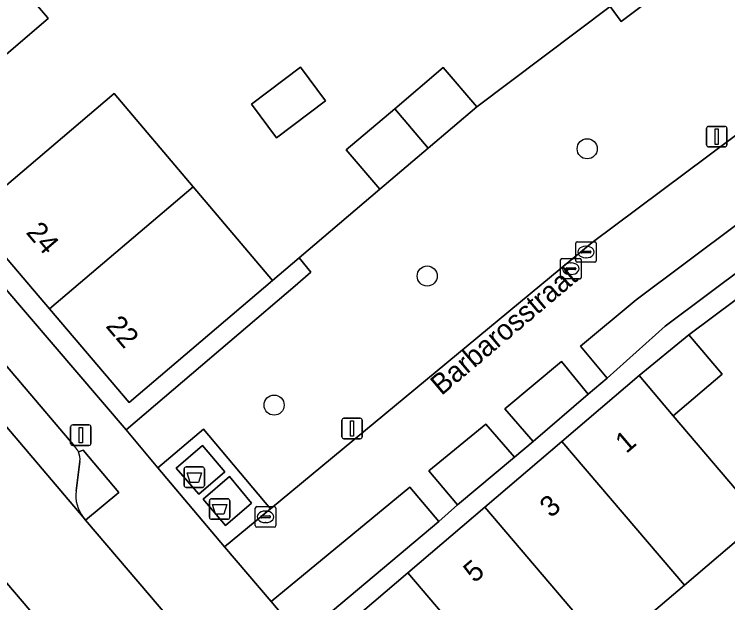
# Model space of a CAD drawing. Extents: x 160377 to 161131, y 383938 to 384853.
# Drawn here: x 160564.71 to 160599.42, y 384590.53 to 384619.15 of the extents above; entities that cross this region are included whole.
import ezdxf

# ---------------------------------------------------------------- set-up
doc = ezdxf.new("R2010")
doc.units = 0
for name, color, linetype in [('IMGEO_Afval_apart_plaats', 7, 'Continuous'), ('IMGEO_Boom', 7, 'Continuous'), ('IMGEO_Erf', 7, 'Continuous'), ('IMGEO_Groenvoorziening', 7, 'Continuous'), ('IMGEO_Kolk', 7, 'Continuous'), ('IMGEO_Lichtmast', 7, 'Continuous'), ('IMGEO_Openbare_ruimte_label', 7, 'Continuous'), ('IMGEO_Pand', 7, 'Continuous'), ('IMGEO_Pand_nummerreeks', 7, 'Continuous'), ('IMGEO_Parkeervlak_open', 7, 'Continuous'), ('IMGEO_Rijbaan_lokaal_open', 7, 'Continuous'), ('IMGEO_Rioolput', 7, 'Continuous'), ('IMGEO_Voetgangersgebied_open', 7, 'Continuous'), ('IMGEO_Voetpad_gesloten', 7, 'Continuous'), ('IMGEO_Voetpad_open', 7, 'Continuous')]:
    doc.layers.add(name, color=color, linetype=linetype)

msp = doc.modelspace()

# ---------------------------------------------------------------- linework, layer by layer
at = {"layer": 'IMGEO_Afval_apart_plaats'}
for p, q in [((160573.078, 384597.139), (160573.868, 384597.139)), ((160573.868, 384597.139), (160573.078, 384597.139)), ((160572.978, 384596.239), (160572.978, 384597.039)), ((160572.978, 384597.039), (160572.978, 384596.239)), ((160573.968, 384597.039), (160573.968, 384596.239)), ((160573.968, 384596.239), (160573.968, 384597.039)), ((160573.868, 384596.139), (160573.078, 384596.139)), ((160573.078, 384596.139), (160573.868, 384596.139)), ((160574.208, 384594.689), (160574.208, 384595.489)), ((160574.208, 384595.489), (160574.208, 384594.689)), ((160574.308, 384595.589), (160575.098, 384595.589)), ((160575.098, 384595.589), (160574.308, 384595.589)), ((160575.198, 384595.489), (160575.198, 384594.689)), ((160575.198, 384594.689), (160575.198, 384595.489)), ((160575.098, 384594.589), (160574.308, 384594.589)), ((160574.308, 384594.589), (160575.098, 384594.589))]:
    msp.add_line(p, q, dxfattribs=at)
for points in [[(160573.121, 384596.853), (160573.825, 384596.853), (160573.676, 384596.383), (160573.27, 384596.383), (160573.121, 384596.853)], [(160574.351, 384595.303), (160575.055, 384595.303), (160574.906, 384594.833), (160574.5, 384594.833), (160574.351, 384595.303)]]:
    msp.add_lwpolyline(points, dxfattribs=at)
for centre, start, end in [((160573.078, 384597.039), 90, 180), ((160573.078, 384597.039), 90, 180), ((160573.868, 384597.039), 0, 90), ((160573.868, 384597.039), 360, 90), ((160573.078, 384596.239), 180, 270), ((160573.078, 384596.239), 180, 270), ((160573.868, 384596.239), 270, 0), ((160573.868, 384596.239), 270, 0), ((160574.308, 384595.489), 90, 180), ((160574.308, 384595.489), 90, 180), ((160575.098, 384595.489), 0, 90), ((160575.098, 384595.489), 360, 90), ((160574.308, 384594.689), 180, 270), ((160574.308, 384594.689), 180, 270), ((160575.098, 384594.689), 270, 0), ((160575.098, 384594.689), 270, 0)]:
    msp.add_arc(centre, 0.1, start, end, dxfattribs=at)
at = {"layer": 'IMGEO_Boom'}
for centre in [(160592.589, 384612.611), (160584.803, 384606.421), (160577.354, 384600.144)]:
    msp.add_circle(centre, 0.489, dxfattribs=at)
at = {"layer": 'IMGEO_Erf'}
for points in [[(160593.711, 384619.536), (160594.236, 384618.794), (160600.544, 384623.533)], [(160562.78, 384623.153), (160566.325, 384618.994), (160566.361, 384618.952), (160559.441, 384613.028), (160559.422, 384613.011), (160558.691, 384612.377), (160561.787, 384608.701), (160562.572, 384609.354), (160569.566, 384615.295), (160573.423, 384610.752), (160577.28, 384606.208), (160578.569, 384607.304), (160582.493, 384610.638), (160580.864, 384612.554), (160583.222, 384614.558), (160585.584, 384616.565), (160587.217, 384614.645), (160593.711, 384619.536)], [(160591.976, 384574.85), (160586.069, 384581.798), (160580.11, 384588.786), (160583.86, 384591.983), (160587.609, 384595.179), (160591.358, 384598.376), (160595.112, 384601.577), (160597.527, 384603.553), (160604.448, 384608.711), (160611.793, 384614.232), (160615.064, 384609.881), (160618.338, 384605.528), (160621.611, 384601.175), (160624.884, 384596.822)], [(160624.091, 384582.595), (160620.818, 384586.948), (160617.544, 384591.3), (160614.27, 384595.653), (160610.996, 384600.006), (160607.722, 384604.358), (160604.448, 384608.711), (160597.527, 384603.553), (160599.148, 384601.649), (160596.772, 384599.627), (160601.065, 384594.584), (160597.316, 384591.387), (160593.567, 384588.191), (160596.062, 384585.072), (160592.408, 384581.957), (160589.818, 384584.995), (160586.069, 384581.798), (160591.976, 384574.85)]]:
    msp.add_lwpolyline(points, dxfattribs=at)
for points in [[(160578.635, 384616.574), (160579.852, 384614.949), (160577.464, 384613.145), (160576.251, 384614.774)], [(160656.048, 384504.315), (160656.893, 384504.376), (160651.516, 384563.083), (160634.758, 384585.358), (160611.972, 384615.646), (160608.482, 384613.028), (160596.383, 384603.983), (160593.555, 384601.453), (160592.642, 384600.679), (160589.954, 384598.377), (160589.048, 384597.617), (160586.272, 384595.285), (160585.368, 384594.478), (160578.674, 384588.862), (160588.469, 384577.392), (160609.42, 384552.826), (160611.199, 384533.452), (160614.226, 384500.488)], [(160578.387, 384605.942), (160579.15, 384606.609), (160578.569, 384607.304), (160577.28, 384606.208), (160570.304, 384600.269), (160566.433, 384604.818), (160562.572, 384609.354), (160561.787, 384608.701), (160570.15, 384598.933)]]:
    msp.add_lwpolyline(points, close=True, dxfattribs=at)
at = {"layer": 'IMGEO_Groenvoorziening'}
for points in [[(160605.23, 384617.306), (160600.544, 384623.533), (160594.236, 384618.794), (160593.711, 384619.536), (160587.217, 384614.645), (160584.857, 384612.643), (160582.493, 384610.638), (160578.569, 384607.304), (160579.15, 384606.609), (160578.387, 384605.942), (160570.15, 384598.933), (160571.697, 384597.097), (160573.915, 384598.966), (160577.172, 384595.101), (160592.826, 384608.058)], [(160608.482, 384613.028), (160607.339, 384614.528), (160594.964, 384605.267), (160592.267, 384603.016), (160593.555, 384601.453), (160596.383, 384603.983)], [(160592.642, 384600.679), (160591.339, 384602.256), (160588.574, 384599.969), (160589.954, 384598.377)], [(160589.048, 384597.617), (160587.656, 384599.213), (160584.883, 384596.943), (160586.272, 384595.285)], [(160585.368, 384594.478), (160583.958, 384596.145), (160577.214, 384590.588), (160578.674, 384588.862)]]:
    msp.add_lwpolyline(points, close=True, dxfattribs=at)
for points in [[(160568.066, 384594.689), (160568.182, 384594.551), (160569.797, 384595.89), (160568.06, 384597.946), (160567.836, 384597.868)], [(160567.905, 384597.403), (160567.721, 384595.973)]]:
    msp.add_lwpolyline(points, dxfattribs=at)
for centre, radius, start, end in [((160567.028, 384597.51), 0.884, 353.0213, 23.8595), ((160569.453, 384595.75), 1.746, 172.6643, 217.415)]:
    msp.add_arc(centre, radius, start, end, dxfattribs=at)
at = {"layer": 'IMGEO_Kolk'}
for p, q in [((160592.028, 384607.162), (160592.028, 384608.014)), ((160592.103, 384608.088), (160592.955, 384608.088)), ((160592.516, 384607.868), (160592.541, 384607.868)), ((160593.029, 384608.014), (160593.029, 384607.162)), ((160592.287, 384607.582), (160592.287, 384607.594)), ((160592.725, 384607.545), (160592.327, 384607.545)), ((160592.33, 384607.631), (160592.728, 384607.631)), ((160592.771, 384607.594), (160592.771, 384607.582)), ((160592.539, 384607.308), (160592.514, 384607.308)), ((160592.955, 384607.088), (160592.103, 384607.088)), ((160576.437, 384594.282), (160576.437, 384595.134)), ((160576.512, 384595.208), (160577.364, 384595.208)), ((160577.438, 384595.134), (160577.438, 384594.282)), ((160576.696, 384594.702), (160576.696, 384594.714)), ((160577.134, 384594.665), (160576.736, 384594.665)), ((160576.739, 384594.751), (160577.137, 384594.751)), ((160576.925, 384594.988), (160576.95, 384594.988)), ((160577.18, 384594.714), (160577.18, 384594.702)), ((160576.948, 384594.428), (160576.923, 384594.428)), ((160577.364, 384594.208), (160576.512, 384594.208))]:
    msp.add_line(p, q, dxfattribs=at)
for points in [[(160592.028, 384607.162), (160592.028, 384608.014)], [(160592.103, 384608.088), (160592.955, 384608.088)], [(160593.029, 384608.014), (160593.029, 384607.162)], [(160592.955, 384607.088), (160592.103, 384607.088)], [(160576.437, 384594.282), (160576.437, 384595.134)], [(160576.512, 384595.208), (160577.364, 384595.208)], [(160577.438, 384595.134), (160577.438, 384594.282)], [(160577.364, 384594.208), (160576.512, 384594.208)]]:
    msp.add_lwpolyline(points, dxfattribs=at)
for centre, radius, start, end in [((160592.105, 384608.012), 0.0765, 91.552, 178.448), ((160592.105, 384608.012), 0.0765, 91.552, 178.448), ((160592.953, 384608.012), 0.0765, 1.552, 88.448), ((160592.953, 384608.012), 0.0765, 1.552, 88.448), ((160592.327, 384607.591), 0.0403, 85.8775, 175.7526), ((160592.324, 384607.581), 0.0366, 178.938, 274.7102), ((160592.728, 384607.588), 0.043, 264.8664, 352.4533), ((160592.732, 384607.593), 0.0386, 1.7309, 96.639), ((160592.105, 384607.164), 0.0765, 181.552, 268.448), ((160592.105, 384607.164), 0.0765, 181.552, 268.448), ((160592.953, 384607.164), 0.0765, 271.552, 358.448), ((160592.953, 384607.164), 0.0765, 271.552, 358.448), ((160576.514, 384595.132), 0.0765, 91.552, 178.448), ((160576.514, 384595.132), 0.0765, 91.552, 178.448), ((160577.362, 384595.132), 0.0765, 1.552, 88.448), ((160577.362, 384595.132), 0.0765, 1.552, 88.448), ((160576.736, 384594.711), 0.0403, 85.8775, 175.7526), ((160576.733, 384594.701), 0.0366, 178.938, 274.7102), ((160577.137, 384594.708), 0.043, 264.8664, 352.4533), ((160577.141, 384594.713), 0.0386, 1.7309, 96.639), ((160576.514, 384594.284), 0.0765, 181.552, 268.448), ((160576.514, 384594.284), 0.0765, 181.552, 268.448), ((160577.362, 384594.284), 0.0765, 271.552, 358.448), ((160577.362, 384594.284), 0.0765, 271.552, 358.448)]:
    msp.add_arc(centre, radius, start, end, dxfattribs=at)
for centre, major_axis, ratio, start_param, end_param in [((160592.515, 384607.588), (-0.387, 0.002), 0.722429, 4.712389, 7.853982), ((160592.54, 384607.588), (-0.39, 0.002), 0.717154, 1.570796, 4.712389), ((160576.924, 384594.708), (-0.387, 0.002), 0.722429, 4.712389, 7.853982), ((160576.949, 384594.708), (-0.39, 0.002), 0.717154, 1.570796, 4.712389)]:
    msp.add_ellipse(centre, major_axis=major_axis, ratio=ratio, start_param=start_param, end_param=end_param, dxfattribs=at)
at = {"layer": 'IMGEO_Lichtmast'}
for p, q in [((160598.393, 384612.8), (160598.393, 384613.6)), ((160598.393, 384613.6), (160598.393, 384612.8)), ((160598.493, 384613.7), (160599.283, 384613.7)), ((160599.283, 384613.7), (160598.493, 384613.7)), ((160599.383, 384613.6), (160599.383, 384612.8)), ((160599.383, 384612.8), (160599.383, 384613.6)), ((160599.283, 384612.7), (160598.493, 384612.7)), ((160598.493, 384612.7), (160599.283, 384612.7)), ((160567.556, 384599.18), (160568.346, 384599.18)), ((160568.346, 384599.18), (160567.556, 384599.18)), ((160580.654, 384598.605), (160580.654, 384599.405)), ((160580.654, 384599.405), (160580.654, 384598.605)), ((160580.754, 384599.505), (160581.544, 384599.505)), ((160581.544, 384599.505), (160580.754, 384599.505)), ((160581.644, 384599.405), (160581.644, 384598.605)), ((160581.644, 384598.605), (160581.644, 384599.405)), ((160567.456, 384598.28), (160567.456, 384599.08)), ((160567.456, 384599.08), (160567.456, 384598.28)), ((160568.446, 384599.08), (160568.446, 384598.28)), ((160568.446, 384598.28), (160568.446, 384599.08)), ((160581.544, 384598.505), (160580.754, 384598.505)), ((160580.754, 384598.505), (160581.544, 384598.505)), ((160568.346, 384598.18), (160567.556, 384598.18)), ((160567.556, 384598.18), (160568.346, 384598.18))]:
    msp.add_line(p, q, dxfattribs=at)
for points in [[(160598.813, 384613.575), (160598.963, 384613.575), (160598.963, 384612.825), (160598.813, 384612.825), (160598.813, 384613.575)], [(160581.074, 384599.38), (160581.224, 384599.38), (160581.224, 384598.63), (160581.074, 384598.63), (160581.074, 384599.38)], [(160567.876, 384599.055), (160568.026, 384599.055), (160568.026, 384598.305), (160567.876, 384598.305), (160567.876, 384599.055)]]:
    msp.add_lwpolyline(points, dxfattribs=at)
for centre, start, end in [((160598.493, 384613.6), 90, 180), ((160598.493, 384613.6), 90, 180), ((160599.283, 384613.6), 0, 90), ((160599.283, 384613.6), 360, 90), ((160598.493, 384612.8), 180, 270), ((160598.493, 384612.8), 180, 270), ((160599.283, 384612.8), 270, 0), ((160599.283, 384612.8), 270, 0), ((160567.556, 384599.08), 90, 180), ((160567.556, 384599.08), 90, 180), ((160568.346, 384599.08), 0, 90), ((160568.346, 384599.08), 360, 90), ((160580.754, 384599.405), 90, 180), ((160580.754, 384599.405), 90, 180), ((160581.544, 384599.405), 0, 90), ((160581.544, 384599.405), 360, 90), ((160580.754, 384598.605), 180, 270), ((160580.754, 384598.605), 180, 270), ((160581.544, 384598.605), 270, 0), ((160581.544, 384598.605), 270, 0), ((160567.556, 384598.28), 180, 270), ((160567.556, 384598.28), 180, 270), ((160568.346, 384598.28), 270, 0), ((160568.346, 384598.28), 270, 0)]:
    msp.add_arc(centre, 0.1, start, end, dxfattribs=at)
at = {"layer": 'IMGEO_Pand'}
for points in [[(160566.361, 384618.952), (160566.325, 384618.994), (160562.78, 384623.153), (160555.833, 384617.232), (160556.83, 384616.065), (160559.348, 384613.089), (160559.422, 384613.011), (160559.441, 384613.028)], [(160576.251, 384614.774), (160577.464, 384613.145), (160579.852, 384614.949), (160578.635, 384616.574)], [(160587.217, 384614.645), (160585.584, 384616.565), (160583.222, 384614.558), (160584.857, 384612.643)], [(160573.423, 384610.752), (160569.566, 384615.295), (160562.572, 384609.354), (160566.433, 384604.818)], [(160584.857, 384612.643), (160583.222, 384614.558), (160580.864, 384612.554), (160582.493, 384610.638)], [(160577.28, 384606.208), (160573.423, 384610.752), (160566.433, 384604.818), (160570.304, 384600.269)], [(160597.527, 384603.553), (160595.112, 384601.577), (160596.772, 384599.627), (160599.148, 384601.649)], [(160596.772, 384599.627), (160595.112, 384601.577), (160591.358, 384598.376), (160597.316, 384591.387), (160601.065, 384594.584)], [(160591.358, 384598.376), (160587.609, 384595.179), (160593.567, 384588.191), (160597.316, 384591.387)], [(160587.609, 384595.179), (160583.86, 384591.983), (160589.818, 384584.995), (160592.408, 384581.957), (160596.062, 384585.072), (160593.567, 384588.191)], [(160583.86, 384591.983), (160580.11, 384588.786), (160586.069, 384581.798), (160589.818, 384584.995)]]:
    msp.add_lwpolyline(points, close=True, dxfattribs=at)
at = {"layer": 'IMGEO_Parkeervlak_open'}
for points in [[(160598.761, 384551.112), (160598.599, 384551.302), (160594.077, 384556.607), (160550.781, 384607.389)], [(160558.988, 384605.381), (160568.066, 384594.689)], [(160567.665, 384598.124), (160562.364, 384604.35)], [(160567.721, 384595.973), (160567.905, 384597.403)]]:
    msp.add_lwpolyline(points, dxfattribs=at)
for centre, radius, start, end in [((160567.024, 384597.511), 0.887, 23.7534, 43.7299), ((160567.028, 384597.51), 0.884, 353.0213, 23.8595), ((160569.453, 384595.75), 1.746, 172.6643, 217.415)]:
    msp.add_arc(centre, radius, start, end, dxfattribs=at)
at = {"layer": 'IMGEO_Rijbaan_lokaal_open'}
msp.add_lwpolyline([(160577.091, 384584.122), (160575.352, 384586.144), (160568.182, 384594.551), (160568.066, 384594.689), (160558.988, 384605.381), (160555.111, 384609.947), (160554.972, 384610.11), (160541.279, 384626.131), (160537.53, 384622.931), (160546.34, 384612.597), (160550.781, 384607.389), (160594.077, 384556.607), (160597.856, 384559.801), (160597.709, 384559.972)], close=True, dxfattribs=at)
at = {"layer": 'IMGEO_Rioolput'}
for p, q in [((160591.291, 384606.351), (160591.291, 384607.203)), ((160591.366, 384607.277), (160592.218, 384607.277)), ((160592.292, 384607.203), (160592.292, 384606.351)), ((160591.593, 384606.82), (160591.991, 384606.82)), ((160591.779, 384607.057), (160591.804, 384607.057)), ((160591.55, 384606.771), (160591.55, 384606.783)), ((160591.988, 384606.734), (160591.59, 384606.734)), ((160591.802, 384606.497), (160591.777, 384606.497)), ((160592.034, 384606.783), (160592.034, 384606.771)), ((160592.218, 384606.277), (160591.366, 384606.277))]:
    msp.add_line(p, q, dxfattribs=at)
for points in [[(160591.291, 384606.351), (160591.291, 384607.203)], [(160591.366, 384607.277), (160592.218, 384607.277)], [(160592.292, 384607.203), (160592.292, 384606.351)], [(160592.218, 384606.277), (160591.366, 384606.277)]]:
    msp.add_lwpolyline(points, dxfattribs=at)
for centre, radius, start, end in [((160591.368, 384607.201), 0.0765, 91.552, 178.448), ((160591.368, 384607.201), 0.0765, 91.552, 178.448), ((160592.216, 384607.201), 0.0765, 1.552, 88.448), ((160592.216, 384607.201), 0.0765, 1.552, 88.448), ((160591.59, 384606.78), 0.0403, 85.8775, 175.7526), ((160591.995, 384606.782), 0.0386, 1.7309, 96.639), ((160591.587, 384606.77), 0.0366, 178.938, 274.7102), ((160591.991, 384606.777), 0.043, 264.8664, 352.4533), ((160591.368, 384606.353), 0.0765, 181.552, 268.448), ((160591.368, 384606.353), 0.0765, 181.552, 268.448), ((160592.216, 384606.353), 0.0765, 271.552, 358.448), ((160592.216, 384606.353), 0.0765, 271.552, 358.448)]:
    msp.add_arc(centre, radius, start, end, dxfattribs=at)
for centre, major_axis, ratio, start_param, end_param in [((160591.778, 384606.777), (-0.387, 0.002), 0.722429, 4.712389, 7.853982), ((160591.803, 384606.777), (-0.39, 0.002), 0.717154, 1.570796, 4.712389)]:
    msp.add_ellipse(centre, major_axis=major_axis, ratio=ratio, start_param=start_param, end_param=end_param, dxfattribs=at)
at = {"layer": 'IMGEO_Voetgangersgebied_open'}
msp.add_lwpolyline([(160592.267, 384603.016), (160594.964, 384605.267), (160607.339, 384614.528), (160605.23, 384617.306), (160592.826, 384608.058), (160577.172, 384595.101), (160574.938, 384593.252), (160577.214, 384590.588), (160583.958, 384596.145), (160585.368, 384594.478), (160586.272, 384595.285), (160584.883, 384596.943), (160587.656, 384599.213), (160589.048, 384597.617), (160589.954, 384598.377), (160588.574, 384599.969), (160591.339, 384602.256), (160592.642, 384600.679), (160593.555, 384601.453)], close=True, dxfattribs=at)
at = {"layer": 'IMGEO_Voetpad_gesloten'}
for points in [[(160572.584, 384597.073), (160573.699, 384595.804), (160574.957, 384596.894), (160573.868, 384598.181)], [(160573.901, 384595.565), (160574.997, 384594.283), (160576.259, 384595.368), (160575.185, 384596.665)]]:
    msp.add_lwpolyline(points, close=True, dxfattribs=at)
at = {"layer": 'IMGEO_Voetpad_open'}
for points in [[(160610.459, 384499.743), (160614.226, 384500.488), (160611.199, 384533.452), (160609.42, 384552.826), (160588.469, 384577.392), (160578.674, 384588.862), (160577.214, 384590.588), (160574.938, 384593.252), (160571.697, 384597.097), (160570.15, 384598.933), (160561.787, 384608.701), (160558.691, 384612.377), (160544.574, 384628.905), (160499.831, 384681.477), (160499.817, 384698.107), (160517.199, 384711.18), (160531.839, 384722.221), (160534.832, 384724.029)], [(160562.364, 384604.35), (160567.665, 384598.124)], [(160567.836, 384597.868), (160568.06, 384597.946), (160569.797, 384595.89), (160568.182, 384594.551), (160575.352, 384586.144), (160576.928, 384587.518), (160580.368, 384583.479), (160580.249, 384583.212)]]:
    msp.add_lwpolyline(points, dxfattribs=at)
for points in [[(160573.915, 384598.966), (160571.697, 384597.097), (160574.938, 384593.252), (160577.172, 384595.101)], [(160572.584, 384597.073), (160573.868, 384598.181), (160574.957, 384596.894), (160573.699, 384595.804)], [(160573.901, 384595.565), (160575.185, 384596.665), (160576.259, 384595.368), (160574.997, 384594.283)]]:
    msp.add_lwpolyline(points, close=True, dxfattribs=at)
msp.add_arc((160567.024, 384597.511), 0.887, 23.7534, 43.7299, dxfattribs=at)

# ---------------------------------------------------------------- texts
at = {"layer": 'IMGEO_Openbare_ruimte_label'}
msp.add_text('Barbarosstraat', height=1, rotation=40.2532, dxfattribs=at).set_placement((160585.496, 384600.577))
at = {"layer": 'IMGEO_Pand_nummerreeks'}
for s, rotation, p in [('24', 310.399, (160565.247, 384608.526)), ('22', 310.399, (160569.125, 384603.969)), ('1', 40.4508, (160594.488, 384597.759)), ('3', 40.4508, (160590.815, 384594.628)), ('5', 40.4508, (160587.1, 384591.46))]:
    msp.add_text(s, height=1, rotation=rotation, dxfattribs=at).set_placement(p)

doc.saveas('drawing.dxf')
